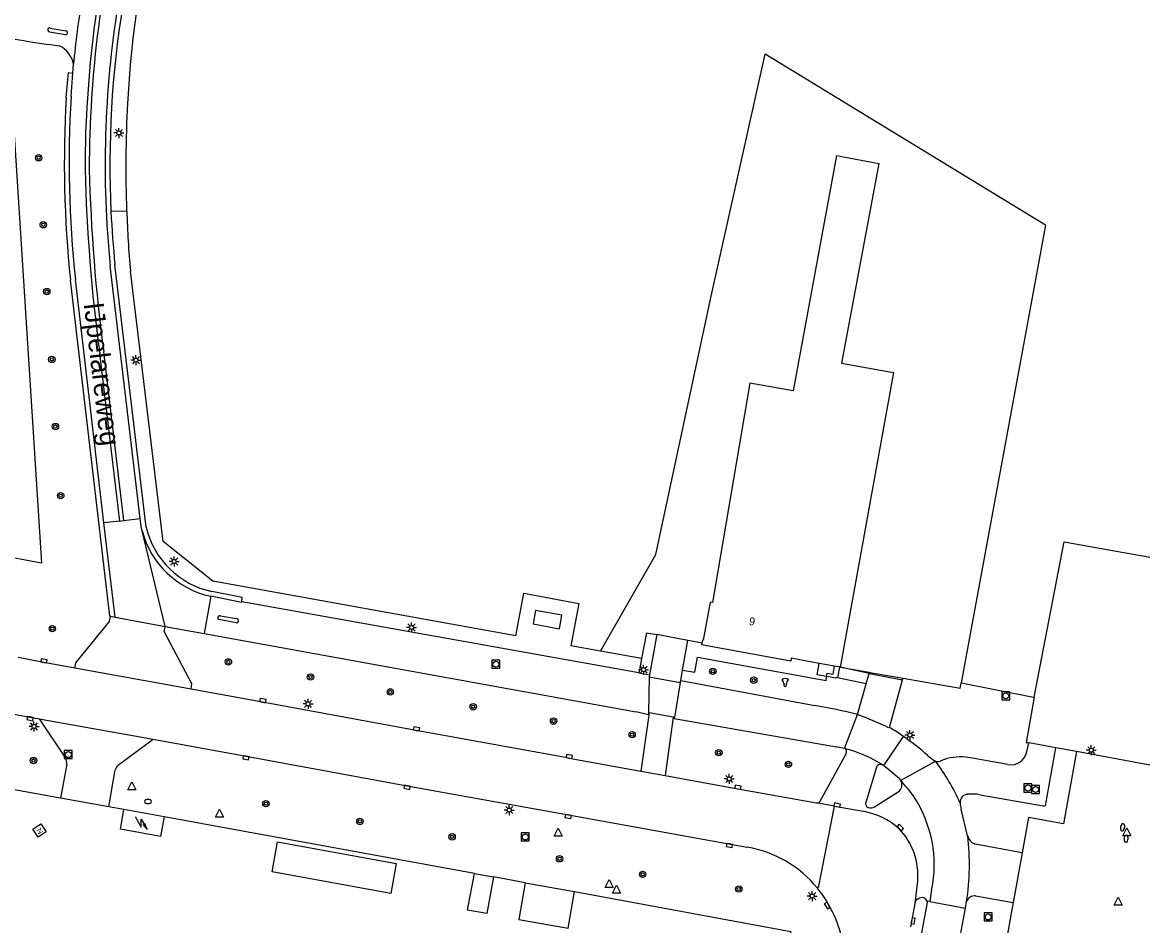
# Model space of a CAD drawing. Extents: x 130998 to 133001, y 398999 to 403002.
# Drawn here: x 132708.1 to 132848.1, y 400111.1 to 400223.9 of the extents above; entities that cross this region are included whole.
import ezdxf

# ---------------------------------------------------------------- set-up
doc = ezdxf.new("R2010")
doc.units = 0
for name, color, linetype in [('gg-afsc-draadraster', 7, 'Continuous'), ('gg-afsc-hekwerk', 7, 'Continuous'), ('gg-afsc-lijn draadraster', 7, 'Continuous'), ('gg-anno-huisnummerreeks BGT', 7, 'Continuous'), ('gg-anno-openbare ruimte label', 7, 'Continuous'), ('gg-bbg-bijgebouw', 7, 'Continuous'), ('gg-bbg-gedigitaliseerde bijgebouw', 7, 'Continuous'), ('gg-bbg-hoofdgebouw', 7, 'Continuous'), ('gg-bbg-hoogspanningsmast', 7, 'Continuous'), ('gg-bbg-lage trafo', 7, 'Continuous'), ('gg-knt-bronhoudergrens', 7, 'Continuous'), ('gg-knt-trap', 7, 'Continuous'), ('gg-knt-verharding', 7, 'Continuous'), ('gg-knt-verharding nz', 7, 'Continuous'), ('gt-grn-groengrens', 7, 'Continuous'), ('gt-grn-vlakafsluiter', 7, 'Continuous'), ('gt-grn-weggrens', 7, 'Continuous'), ('gt-symb-boom', 7, 'Continuous'), ('gt-symb-brandkraan', 7, 'Continuous'), ('gt-symb-kolk', 7, 'Continuous'), ('gt-symb-lichtmast', 7, 'Continuous'), ('gt-symb-nortonput', 7, 'Continuous'), ('gt-symb-rioolschacht', 7, 'Continuous'), ('gt-symb-sirene', 7, 'Continuous'), ('gt-symb-trafo symbool', 7, 'Continuous'), ('gt-symb-waterafsluiter', 7, 'Continuous')]:
    doc.layers.add(name, color=color, linetype=linetype)

# ---------------------------------------------------------------- blocks, each defined once
blk = doc.blocks.new('gt0-WAFSL')
at = {"layer": 'gt-symb-waterafsluiter'}
for p, q in [((-0.5, -0.33), (0, 0.67)), ((0, 0.67), (0.5, -0.33)), ((0.5, -0.33), (-0.5, -0.33))]:
    blk.add_line(p, q, dxfattribs=at)
blk = doc.blocks.new('gt0-BR')
at = {"layer": 'gt-symb-brandkraan'}
for centre, radius, start, end in [((-0.24, 0), 0.206, 107.5669, 252.4331), ((0.6, -2.66), 3, 106.892, 107.5669), ((0, -0.69), 0.938, 73.108, 106.892), ((-0.6, -2.66), 3, 72.4331, 73.108), ((0.24, 0), 0.206, 287.567, 72.4331), ((0.6, 2.66), 3, 252.4331, 253.108), ((0, 0.69), 0.938, 253.108, 286.8921), ((-0.6, 2.66), 3, 286.8921, 287.567)]:
    blk.add_arc(centre, radius, start, end, dxfattribs=at)
blk = doc.blocks.new('gt0-LMAST')
at = {"layer": 'gt-symb-lichtmast'}
for p, q in [((-0.18, 0.17), (-0.45, 0.44)), ((-0.01, 0.25), (-0.01, 0.62)), ((0.17, 0.17), (0.44, 0.44)), ((-0.26, 0), (-0.63, 0)), ((-0.18, -0.18), (-0.45, -0.45)), ((-0.01, -0.25), (-0.01, -0.63)), ((0.44, -0.45), (0.17, -0.18)), ((0.24, 0), (0.62, 0))]:
    blk.add_line(p, q, dxfattribs=at)
blk.add_circle((-0.01, 0), 0.25, dxfattribs=at)
blk = doc.blocks.new('gt0-RS')
at = {"layer": 'gt-symb-rioolschacht'}
blk.add_lwpolyline([(-0.5, -0.5), (0.5, -0.5), (0.5, 0.5), (-0.5, 0.5)], close=True, dxfattribs=at)
blk.add_circle((0, 0), 0.375, dxfattribs=at)
blk = doc.blocks.new('gt0-BOOM')
at = {"layer": 'gt-symb-boom'}
for radius in [0.4, 0.2]:
    blk.add_circle((0, 0), radius, dxfattribs=at)
blk = doc.blocks.new('gt0-SIRENE')
at = {"layer": 'gt-symb-sirene'}
for centre, radius, start, end in [((0, 0), 0.175, 53.9487, 306.0513), ((-0.06, 1.19), 1.07, 278.7505, 311.9457), ((0.2, 0), 0.605, 318.3805, 41.6195), ((-0.06, -1.19), 1.07, 48.0543, 81.2495)]:
    blk.add_arc(centre, radius, start, end, dxfattribs=at)
blk = doc.blocks.new('gt0-KOLK')
at = {"layer": 'gt-symb-kolk'}
blk.add_lwpolyline([(0, 0), (0.37, 0), (0.37, 0.4), (-0.38, 0.4), (-0.38, 0), (0, 0)], dxfattribs=at)
blk = doc.blocks.new('gt0-NPUT')
at = {"layer": 'gt-symb-nortonput'}
blk.add_lwpolyline([(-0.57, -0.61), (-0.57, 0.59), (0.63, 0.59), (0.63, -0.61)], close=True, dxfattribs=at)
blk.add_text('N', height=0.7, dxfattribs=at).set_placement((-0.22, -0.38))
blk = doc.blocks.new('gt0-HSP')
at = {"layer": 'gt-symb-trafo symbool'}
for points in [[(0.77, 0.75), (-0.53, 0), (0.47, 0), (-0.83, -0.75)], [(-0.22, -0.24), (-0.83, -0.75), (-0.08, -0.48)]]:
    blk.add_lwpolyline(points, dxfattribs=at)

msp = doc.modelspace()

# ---------------------------------------------------------------- linework, layer by layer
at = {"layer": 'gg-afsc-draadraster'}
for q in [(132800.94, 400219.99), (132825.42, 400141.44)]:
    msp.add_line((132835.97, 400198.61), q, dxfattribs=at)
msp.add_lwpolyline([(132834.54, 400139.65), (132838.3, 400159.05), (132859.49, 400155.28), (132859.53, 400155.5)], dxfattribs=at)
at = {"layer": 'gg-afsc-hekwerk'}
for p, q in [((132786.12, 400147.72), (132785.49, 400144.48)), ((132786.12, 400147.72), (132787.41, 400147.48)), ((132791.3, 400146.75), (132787.41, 400147.48)), ((132780.39, 400145.41), (132776.67, 400146.08)), ((132791.99, 400146.62), (132791.3, 400146.75)), ((132793.03, 400146.43), (132791.99, 400146.62)), ((132785.49, 400144.48), (132780.39, 400145.41)), ((132785.49, 400144.48), (132785.23, 400143.07)), ((132810.31, 400143.42), (132813.96, 400142.77)), ((132813.96, 400142.77), (132814.27, 400142.72)), ((132814.27, 400142.72), (132817.23, 400142.2)), ((132817.23, 400142.2), (132818.19, 400142.03)), ((132825.42, 400141.44), (132834.46, 400139.66)), ((132825.42, 400141.44), (132834.46, 400139.66)), ((132834.54, 400139.65), (132833.55, 400134.02)), ((132834.46, 400139.66), (132834.54, 400139.65)), ((132833.55, 400134.02), (132833.74, 400133.99)), ((132833.74, 400133.99), (132833.83, 400133.97)), ((132833.83, 400133.97), (132833.95, 400133.95)), ((132837.27, 400133.33), (132833.95, 400133.95)), ((132839.85, 400132.86), (132837.27, 400133.33)), ((132855.06, 400130.07), (132839.85, 400132.86)), ((132712.89, 400127.06), (132706.9, 400128.14)), ((132718.96, 400125.96), (132712.89, 400127.06)), ((132720.83, 400125.62), (132718.96, 400125.96)), ((132764.61, 400117.66), (132725.85, 400124.72)), ((132833.05, 400120.24), (132831.92, 400114)), ((132831.92, 400114), (132831.64, 400112.45)), ((132831.64, 400112.45), (132825.75, 400079.99))]:
    msp.add_line(p, q, dxfattribs=at)
for points in [[(132703.28, 400157.73), (132624.76, 400172.1), (132627.85, 400186.54), (132635.3, 400209.39), (132646.6, 400234.95), (132652.41, 400233.02), (132658.28, 400231.31), (132666.83, 400229.25), (132706.39, 400221.06), (132710.52, 400156.41), (132704.7, 400157.47)], [(132769.81, 400147.32), (132731.95, 400154.15), (132725.74, 400159.11), (132721.63, 400192.86)], [(132769.81, 400147.32), (132770.79, 400152.67), (132777.65, 400151.38), (132776.67, 400146.08)], [(132818.19, 400142.03), (132825.3, 400140.77), (132825.42, 400141.44)], [(132839.85, 400132.86), (132838.23, 400123.85), (132833.85, 400124.62), (132833.05, 400120.24)], [(132777.14, 400115.39), (132804.14, 400110.39), (132802.25, 400099.76)]]:
    msp.add_lwpolyline(points, dxfattribs=at)
for centre, radius, start, end in [((132846.27, 400207.76), 125.13, 159.3647, 177.2216), ((132875.88, 400205.89), 154.81, 177.0595, 182.037), ((132876.36, 400205.91), 155.28, 182.0408, 184.8216)]:
    msp.add_arc(centre, radius, start, end, dxfattribs=at)
at = {"layer": 'gg-afsc-lijn draadraster'}
for q in [(132800.94, 400219.99), (132825.42, 400141.44)]:
    msp.add_line((132835.97, 400198.61), q, dxfattribs=at)
at = {"layer": 'gg-bbg-bijgebouw'}
for p, q in [((132725.85, 400124.72), (132720.83, 400125.62)), ((132764.61, 400117.66), (132767.02, 400117.22)), ((132770.98, 400116.49), (132777.14, 400115.39))]:
    msp.add_line(p, q, dxfattribs=at)
for points in [[(132725.85, 400124.72), (132725.4, 400122.26), (132720.39, 400123.16), (132720.83, 400125.62)], [(132767.02, 400117.22), (132766.18, 400112.64), (132763.76, 400113.08), (132764.61, 400117.66)], [(132770.98, 400116.49), (132770.15, 400111.91), (132776.32, 400110.81), (132777.14, 400115.39)]]:
    msp.add_lwpolyline(points, dxfattribs=at)
at = {"layer": 'gg-bbg-gedigitaliseerde bijgebouw'}
msp.add_lwpolyline([(132740.02, 400121.59), (132754.86, 400118.89), (132754.18, 400115.15), (132739.34, 400117.85), (132740.02, 400121.59)], dxfattribs=at)
at = {"layer": 'gg-bbg-hoofdgebouw'}
for p, q in [((132793.03, 400146.43), (132792.99, 400146.2)), ((132809.63, 400143.54), (132807.71, 400143.89)), ((132810.23, 400143.44), (132809.63, 400143.54)), ((132810.31, 400143.42), (132810.23, 400143.44))]:
    msp.add_line(p, q, dxfattribs=at)
for points in [[(132809.88, 400207.31), (132804.46, 400177.91), (132799.05, 400178.9), (132794.35, 400151.47), (132794.07, 400151.52), (132793.21, 400146.77), (132793.1, 400146.79), (132793.03, 400146.43)], [(132809.88, 400207.31), (132815.14, 400206.34), (132810.49, 400181.37), (132816.98, 400180.2), (132810.31, 400143.42)], [(132807.71, 400143.89), (132804.21, 400144.52), (132804.15, 400144.18), (132792.99, 400146.2)]]:
    msp.add_lwpolyline(points, dxfattribs=at)
at = {"layer": 'gg-bbg-hoogspanningsmast'}
msp.add_line((132770.98, 400116.49), (132767.02, 400117.22), dxfattribs=at)
at = {"layer": 'gg-bbg-lage trafo'}
msp.add_lwpolyline([(132772.24, 400150.49), (132771.94, 400148.81), (132775.25, 400148.22), (132775.55, 400149.9), (132772.24, 400150.49)], dxfattribs=at)
at = {"layer": 'gg-knt-bronhoudergrens'}
msp.add_lwpolyline([(132780.39, 400145.41), (132787.3, 400157.47), (132794.18, 400189.75), (132800.94, 400219.99)], dxfattribs=at)
at = {"layer": 'gg-knt-trap'}
msp.add_line((132810.23, 400143.44), (132809.99, 400142.09), dxfattribs=at)
for points in [[(132808.62, 400142.24), (132808.71, 400142.67), (132809.45, 400142.55), (132809.63, 400143.54)], [(132809.99, 400142.09), (132809.76, 400142.12), (132809.76, 400142.06), (132808.62, 400142.24)]]:
    msp.add_lwpolyline(points, dxfattribs=at)
at = {"layer": 'gg-knt-verharding'}
for p, q in [((132713.54, 400222.4), (132711.53, 400222.75)), ((132711.63, 400223.25), (132713.57, 400222.91)), ((132714.46, 400217.62), (132714.53, 400218.74)), ((132714.22, 400214.69), (132714.46, 400217.62)), ((132722.87, 400161.98), (132719.12, 400193.54)), ((132723.6, 400160.89), (132719.71, 400193.69)), ((132718.33, 400161.44), (132714.76, 400191.85)), ((132719.72, 400149.65), (132718.33, 400161.44)), ((132785.16, 400142.69), (132735.54, 400151.57)), ((132732.88, 400149.82), (132734.87, 400149.49)), ((132719.15, 400149.77), (132719.72, 400149.65)), ((132719.72, 400149.65), (132725.97, 400148.51)), ((132725.97, 400148.51), (132730.84, 400147.62)), ((132734.85, 400148.97), (132732.73, 400149.35)), ((132730.84, 400147.62), (132784.85, 400137.85)), ((132787.41, 400147.48), (132786.49, 400142.44)), ((132790.6, 400143.03), (132791.3, 400146.75)), ((132729.21, 400140.67), (132714.7, 400143.3)), ((132790.39, 400141.74), (132790.6, 400143.03)), ((132813.93, 400142.63), (132810.31, 400143.42)), ((132785.16, 400142.69), (132786.49, 400142.44)), ((132786.49, 400142.44), (132786.46, 400142.2)), ((132786.46, 400142.2), (132790.34, 400141.51)), ((132790.34, 400141.51), (132790.39, 400141.74)), ((132790.39, 400141.74), (132807.16, 400138.61)), ((132813.58, 400141.34), (132809.99, 400142.09)), ((132813.58, 400141.34), (132813.93, 400142.63)), ((132813.96, 400142.77), (132813.93, 400142.63)), ((132813.93, 400142.63), (132818.12, 400141.83)), ((132816.5, 400135.86), (132818.12, 400141.83)), ((132818.12, 400141.83), (132818.19, 400142.03)), ((132812.48, 400137.49), (132813.58, 400141.34)), ((132694.99, 400139.77), (132710.24, 400136.98)), ((132786.45, 400137.69), (132785.43, 400130.43)), ((132786.45, 400137.69), (132786.38, 400137.7)), ((132789.45, 400137.16), (132786.45, 400137.69)), ((132710.24, 400136.98), (132713.52, 400132.04)), ((132710.24, 400136.98), (132724.46, 400134.4)), ((132789.45, 400137.16), (132788.46, 400129.89)), ((132789.61, 400137.13), (132789.45, 400137.16)), ((132720.15, 400131.21), (132724.46, 400134.4)), ((132833.83, 400133.97), (132833.62, 400132.84)), ((132836.03, 400126.34), (132837.27, 400133.33)), ((132776.44, 400132.06), (132785.43, 400130.43)), ((132807.83, 400126.68), (132811.05, 400132.6)), ((132823.33, 400131.86), (132822.8, 400131.66)), ((132831.28, 400131.24), (132826.35, 400132.12)), ((132713.68, 400131.29), (132712.89, 400127.06)), ((132718.96, 400125.96), (132719.75, 400130.58)), ((132785.43, 400130.43), (132788.46, 400129.89)), ((132814.85, 400130.91), (132813.51, 400126.5)), ((132815.76, 400131.13), (132815.46, 400131.23)), ((132814.61, 400125.96), (132817.56, 400127.85)), ((132827.81, 400127.48), (132835.7, 400126.09)), ((132809.62, 400126.04), (132807.38, 400126.46)), ((132826.24, 400122.33), (132825.42, 400125.69)), ((132833.05, 400120.24), (132827.2, 400121.32)), ((132821.75, 400115.58), (132821.51, 400114.14)), ((132827.24, 400114.84), (132831.92, 400114)), ((132819.64, 400113.89), (132819.09, 400110.96)), ((132821.51, 400114.14), (132821.18, 400114.18)), ((132825.96, 400113.33), (132826.11, 400114.13)), ((132822.89, 400096.31), (132825.96, 400113.33))]:
    msp.add_line(p, q, dxfattribs=at)
for points in [[(132713.62, 400214.59), (132713.89, 400217.7), (132714.46, 400217.62)], [(132719.15, 400149.77), (132719.06, 400149.77), (132714.14, 400191.77)], [(132723.12, 400160.43), (132722.98, 400161), (132722.87, 400161.98)], [(132735.54, 400151.57), (132735.62, 400152.11), (132731.8, 400152.86)], [(132735.54, 400151.57), (132735.52, 400151.51), (132731.68, 400152.28)], [(132714.7, 400143.3), (132714.81, 400143.96), (132719.03, 400149.12), (132719.15, 400149.77)], [(132729.21, 400140.67), (132729.32, 400141.32), (132725.85, 400147.88), (132725.97, 400148.51)], [(132714.7, 400143.3), (132710.8, 400144), (132707.6, 400144.6)], [(132790.6, 400143.03), (132792.17, 400142.79), (132792.5, 400144.68), (132808.58, 400141.75), (132808.62, 400142.24)], [(132808.62, 400142.24), (132807.45, 400142.45), (132807.71, 400143.89)], [(132776.44, 400132.06), (132757.36, 400135.51), (132738.16, 400139.04), (132729.21, 400140.67)], [(132786.38, 400137.7), (132786.35, 400137.47), (132784.85, 400137.85)], [(132810.84, 400133.27), (132809.83, 400133.47), (132809.84, 400133.43), (132789.59, 400136.97), (132789.61, 400137.13)], [(132816.38, 400135.86), (132816.41, 400135.93), (132816.5, 400135.86)], [(132724.46, 400134.4), (132736.1, 400132.28), (132756.23, 400128.61), (132776.37, 400124.96), (132798.71, 400120.93)], [(132822.24, 400131.66), (132822.07, 400131.72), (132821.25, 400132.33), (132821.28, 400132.38)], [(132815.76, 400131.13), (132816.15, 400130.85), (132817.69, 400129.54), (132817.87, 400129.24)], [(132788.46, 400129.89), (132797.52, 400128.23), (132807.38, 400126.46)], [(132807.47, 400115.82), (132807.66, 400116.06), (132809.62, 400126.04)], [(132821.18, 400114.18), (132821.17, 400114.01), (132820.48, 400110.24)]]:
    msp.add_lwpolyline(points, dxfattribs=at)
for centre, radius, start, end in [((132843.92, 400206.16), 125.44, 170.8555, 185.7776), ((132842.38, 400206.18), 123.31, 170.7274, 182.7238), ((132711.57, 400223.01), 0.255, 75.9692, 262.7361), ((132713.54, 400222.66), 0.254, 269.7835, 82.7389), ((132730.03, 400356.04), 136.11, 258.9428, 262.715), ((132711.33, 400218.11), 3.26, 11.0815, 63.7755), ((132853.18, 400206.36), 139.8, 176.6255, 185.9904), ((132848.3, 400206.4), 134.33, 176.4635, 186.2201), ((132842.83, 400206.22), 123.76, 182.7341, 185.8106), ((132734.06, 400163.35), 11.33, 194.9275, 257.8478), ((132734.09, 400163.41), 10.79, 193.5164, 257.7689), ((132732.79, 400149.59), 0.249, 69.1315, 256.4766), ((132734.87, 400149.23), 0.262, 264.4131, 91.4177), ((132799.44, 400088.95), 50.26, 74.9669, 81.1744), ((132795.94, 400092.54), 47.89, 64.7476, 69.7997), ((132799.73, 400107.89), 32.62, 55.3947, 59.0454), ((132799.66, 400107.79), 32.74, 48.6701, 55.4021), ((132806.49, 400116.58), 17.25, 57.4878, 75.3685), ((132810.62, 400132.84), 0.49, 331.3228, 62.4368), ((132712.69, 400131.48), 1, 348.9681, 34.0027), ((132801.46, 400115.94), 26.05, 23.8245, 37.1085), ((132822.52, 400132.58), 0.966, 252.6336, 286.9644), ((132825.36, 400126.01), 6.2, 80.7967, 109.0608), ((132831.64, 400133.24), 2.03, 260.0109, 348.5705), ((132720.69, 400130.43), 0.947, 124.6922, 171.1996), ((132815.32, 400130.76), 0.492, 72.6062, 162.4422), ((132817.03, 400128.7), 1.01, 302.2608, 32.4373), ((132808.47, 400119.79), 13.33, 34.0061, 45.1222), ((132826.28, 400126.54), 0.988, 91.8932, 184.6267), ((132826.81, 400121.38), 6.18, 80.6622, 95.2444), ((132807.42, 400126.95), 0.492, 265.2627, 325.6938), ((132814.01, 400126.37), 0.524, 165.7702, 250.6227), ((132806.61, 400118.72), 15.46, 348.257, 33.4321), ((132828.47, 400126.61), 3.18, 182.6541, 196.8463), ((132835.77, 400126.34), 0.258, 253.6964, 359.4858), ((132814.12, 400126.89), 1.05, 254.7725, 298.1368), ((132796.85, 400118.72), 29.62, 351.0814, 7.0052), ((132827.53, 400122.58), 1.3, 190.9729, 255.5979), ((132796.28, 400106.69), 14.44, 39.1972, 80.2851), ((132799.48, 400108.88), 10.58, 27.3649, 40.9545), ((132827.09, 400113.83), 1.02, 81.4284, 163.0008), ((132796.36, 400106.4), 14.51, 14.705, 30.4013), ((132820.57, 400113.66), 0.963, 77.8715, 166.2659), ((132820.57, 400113.99), 0.642, 16.6123, 70.897)]:
    msp.add_arc(centre, radius, start, end, dxfattribs=at)
at = {"layer": 'gg-knt-verharding nz'}
for p, q in [((132717.79, 400182.62), (132720.29, 400161.67)), ((132720.8, 400161.73), (132718.3, 400182.81)), ((132720.29, 400161.67), (132720.8, 400161.73)), ((132725.97, 400148.51), (132723.12, 400160.43)), ((132809.62, 400126.04), (132813.19, 400125.41)), ((132820, 400116.7), (132819.64, 400113.89))]:
    msp.add_line(p, q, dxfattribs=at)
for centre, radius, start, end in [((132857.29, 400205.41), 141.32, 165.4603, 179.9283), ((132857.43, 400205.38), 140.94, 165.4481, 179.9129), ((132826.12, 400208.51), 112.06, 170.5751, 174.7636), ((132930.49, 400211.09), 214.59, 181.4712, 187.6235), ((132930.77, 400211.13), 214.35, 181.4805, 187.5911), ((132811.56, 400116.27), 9.28, 48.6274, 79.8923), ((132811.45, 400117.36), 8.58, 355.5413, 43.2306)]:
    msp.add_arc(centre, radius, start, end, dxfattribs=at)
at = {"layer": 'gt-grn-groengrens'}
msp.add_line((132721.18, 400200.39), (132719.21, 400200.32), dxfattribs=at)
at = {"layer": 'gt-grn-vlakafsluiter'}
msp.add_line((132785.23, 400143.07), (132785.16, 400142.69), dxfattribs=at)
at = {"layer": 'gt-grn-weggrens'}
for p, q in [((132720.29, 400161.67), (132718.33, 400161.44)), ((132720.8, 400161.73), (132722.87, 400161.98)), ((132731.68, 400152.28), (132730.84, 400147.62)), ((132786.46, 400142.2), (132786.38, 400137.7)), ((132790.34, 400141.51), (132789.61, 400137.13)), ((132810.84, 400133.27), (132812.48, 400137.49)), ((132815.76, 400131.13), (132818.25, 400134.74)), ((132817.87, 400129.24), (132822.24, 400131.66)), ((132821.51, 400114.14), (132825.96, 400113.33))]:
    msp.add_line(p, q, dxfattribs=at)

# ---------------------------------------------------------------- block references
at = {"layer": 'gt-symb-boom'}
for p in [(132710.18, 400207.04), (132710.75, 400198.67), (132711.19, 400190.33), (132711.82, 400181.85), (132712.27, 400173.47), (132712.93, 400164.84), (132711.88, 400148.22), (132733.88, 400144.07), (132794.41, 400142.89), (132744.14, 400142.19), (132799.52, 400141.79), (132754.11, 400140.32), (132764.46, 400138.47), (132774.51, 400136.68), (132784.32, 400134.98), (132795.16, 400132.73), (132709.53, 400131.75), (132803.85, 400131.28), (132738.57, 400126.36), (132750.31, 400124.15), (132761.83, 400122.22), (132775.26, 400119.48), (132785.64, 400117.54), (132797.65, 400115.71)]:
    msp.add_blockref('gt0-BOOM', p, dxfattribs=at)
at = {"layer": 'gt-symb-brandkraan'}
msp.add_blockref('gt0-BR', (132723.83, 400126.63), dxfattribs=at)
for p, rotation in [((132845.6, 400123.4), 74.96357992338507), ((132846.04, 400121.99), 84.30948134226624)]:
    msp.add_blockref('gt0-BR', p, dxfattribs=dict(at, rotation=rotation))
at = {"layer": 'gt-symb-kolk'}
for p, rotation in [((132710.8, 400144), -10.13233239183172), ((132738.16, 400139.04), -9.779390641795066), ((132709.13, 400137.19), 169.63813061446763), ((132757.36, 400135.51), -10.26370230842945), ((132736.1, 400132.28), 169.7124760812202), ((132776.44, 400132.06), -10.328665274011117), ((132756.23, 400128.61), 169.6713347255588), ((132797.52, 400128.23), -10.148220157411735), ((132809.91, 400125.99), -10.057998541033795), ((132776.37, 400124.96), 169.72041621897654), ((132817.7, 400123.24), -43.63620827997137), ((132796.51, 400121.33), 169.76155744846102), ((132808.87, 400113.75), 121.17134902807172), ((132819.24, 400111.75), -100.85413344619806)]:
    msp.add_blockref('gt0-KOLK', p, dxfattribs=dict(at, rotation=rotation))
at = {"layer": 'gt-symb-lichtmast'}
for p in [(132720.21, 400210.14), (132722.33, 400181.77), (132727.11, 400156.62), (132756.77, 400148.37), (132785.76, 400143.1), (132743.84, 400138.83), (132709.6, 400136.01), (132819.04, 400134.94), (132841.7, 400133.04), (132796.47, 400129.46), (132768.98, 400125.57), (132806.83, 400114.82)]:
    msp.add_blockref('gt0-LMAST', p, dxfattribs=at)
at = {"layer": 'gt-symb-nortonput', "rotation": -56.4211862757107}
msp.add_blockref('gt0-NPUT', (132710.27, 400123.04), dxfattribs=at)
at = {"layer": 'gt-symb-rioolschacht'}
for p in [(132767.3, 400143.78), (132831.01, 400139.83), (132713.88, 400132.49), (132833.78, 400128.32), (132834.74, 400128.13), (132770.98, 400122.21), (132828.81, 400112.21)]:
    msp.add_blockref('gt0-RS', p, dxfattribs=at)
at = {"layer": 'gt-symb-sirene', "rotation": 90}
msp.add_blockref('gt0-SIRENE', (132803.45, 400141.18), dxfattribs=at)
at = {"layer": 'gt-symb-trafo symbool', "rotation": 90}
msp.add_blockref('gt0-HSP', (132722.97, 400123.97), dxfattribs=at)
at = {"layer": 'gt-symb-waterafsluiter'}
for p in [(132721.82, 400128.44), (132732.76, 400125), (132775.09, 400122.64), (132846.13, 400122.68), (132781.45, 400116.22), (132782.39, 400115.5), (132845.06, 400114.02)]:
    msp.add_blockref('gt0-WAFSL', p, dxfattribs=at)

# ---------------------------------------------------------------- texts
at = {"layer": 'gg-anno-huisnummerreeks BGT'}
msp.add_text('9', height=1, rotation=349.7, dxfattribs=at).set_placement((132798.86, 400148.7))
at = {"layer": 'gg-anno-openbare ruimte label'}
msp.add_text('IJpelareweg', height=2.5, rotation=276.8, dxfattribs=at).set_placement((132715.79, 400188.83))

doc.saveas('drawing.dxf')
